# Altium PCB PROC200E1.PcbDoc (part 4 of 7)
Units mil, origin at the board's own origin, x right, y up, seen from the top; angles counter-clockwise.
Board outline 4163.97 x 3505.34 mil, 6 copper layers (Top Layer, GND1, SIG1, PWR, GND2, Bottom), stack 58.132 mil thick; 367 components, 387 nets, 1784 pads, 858 vias.
Unrouted connection lines stored in the file: 17.
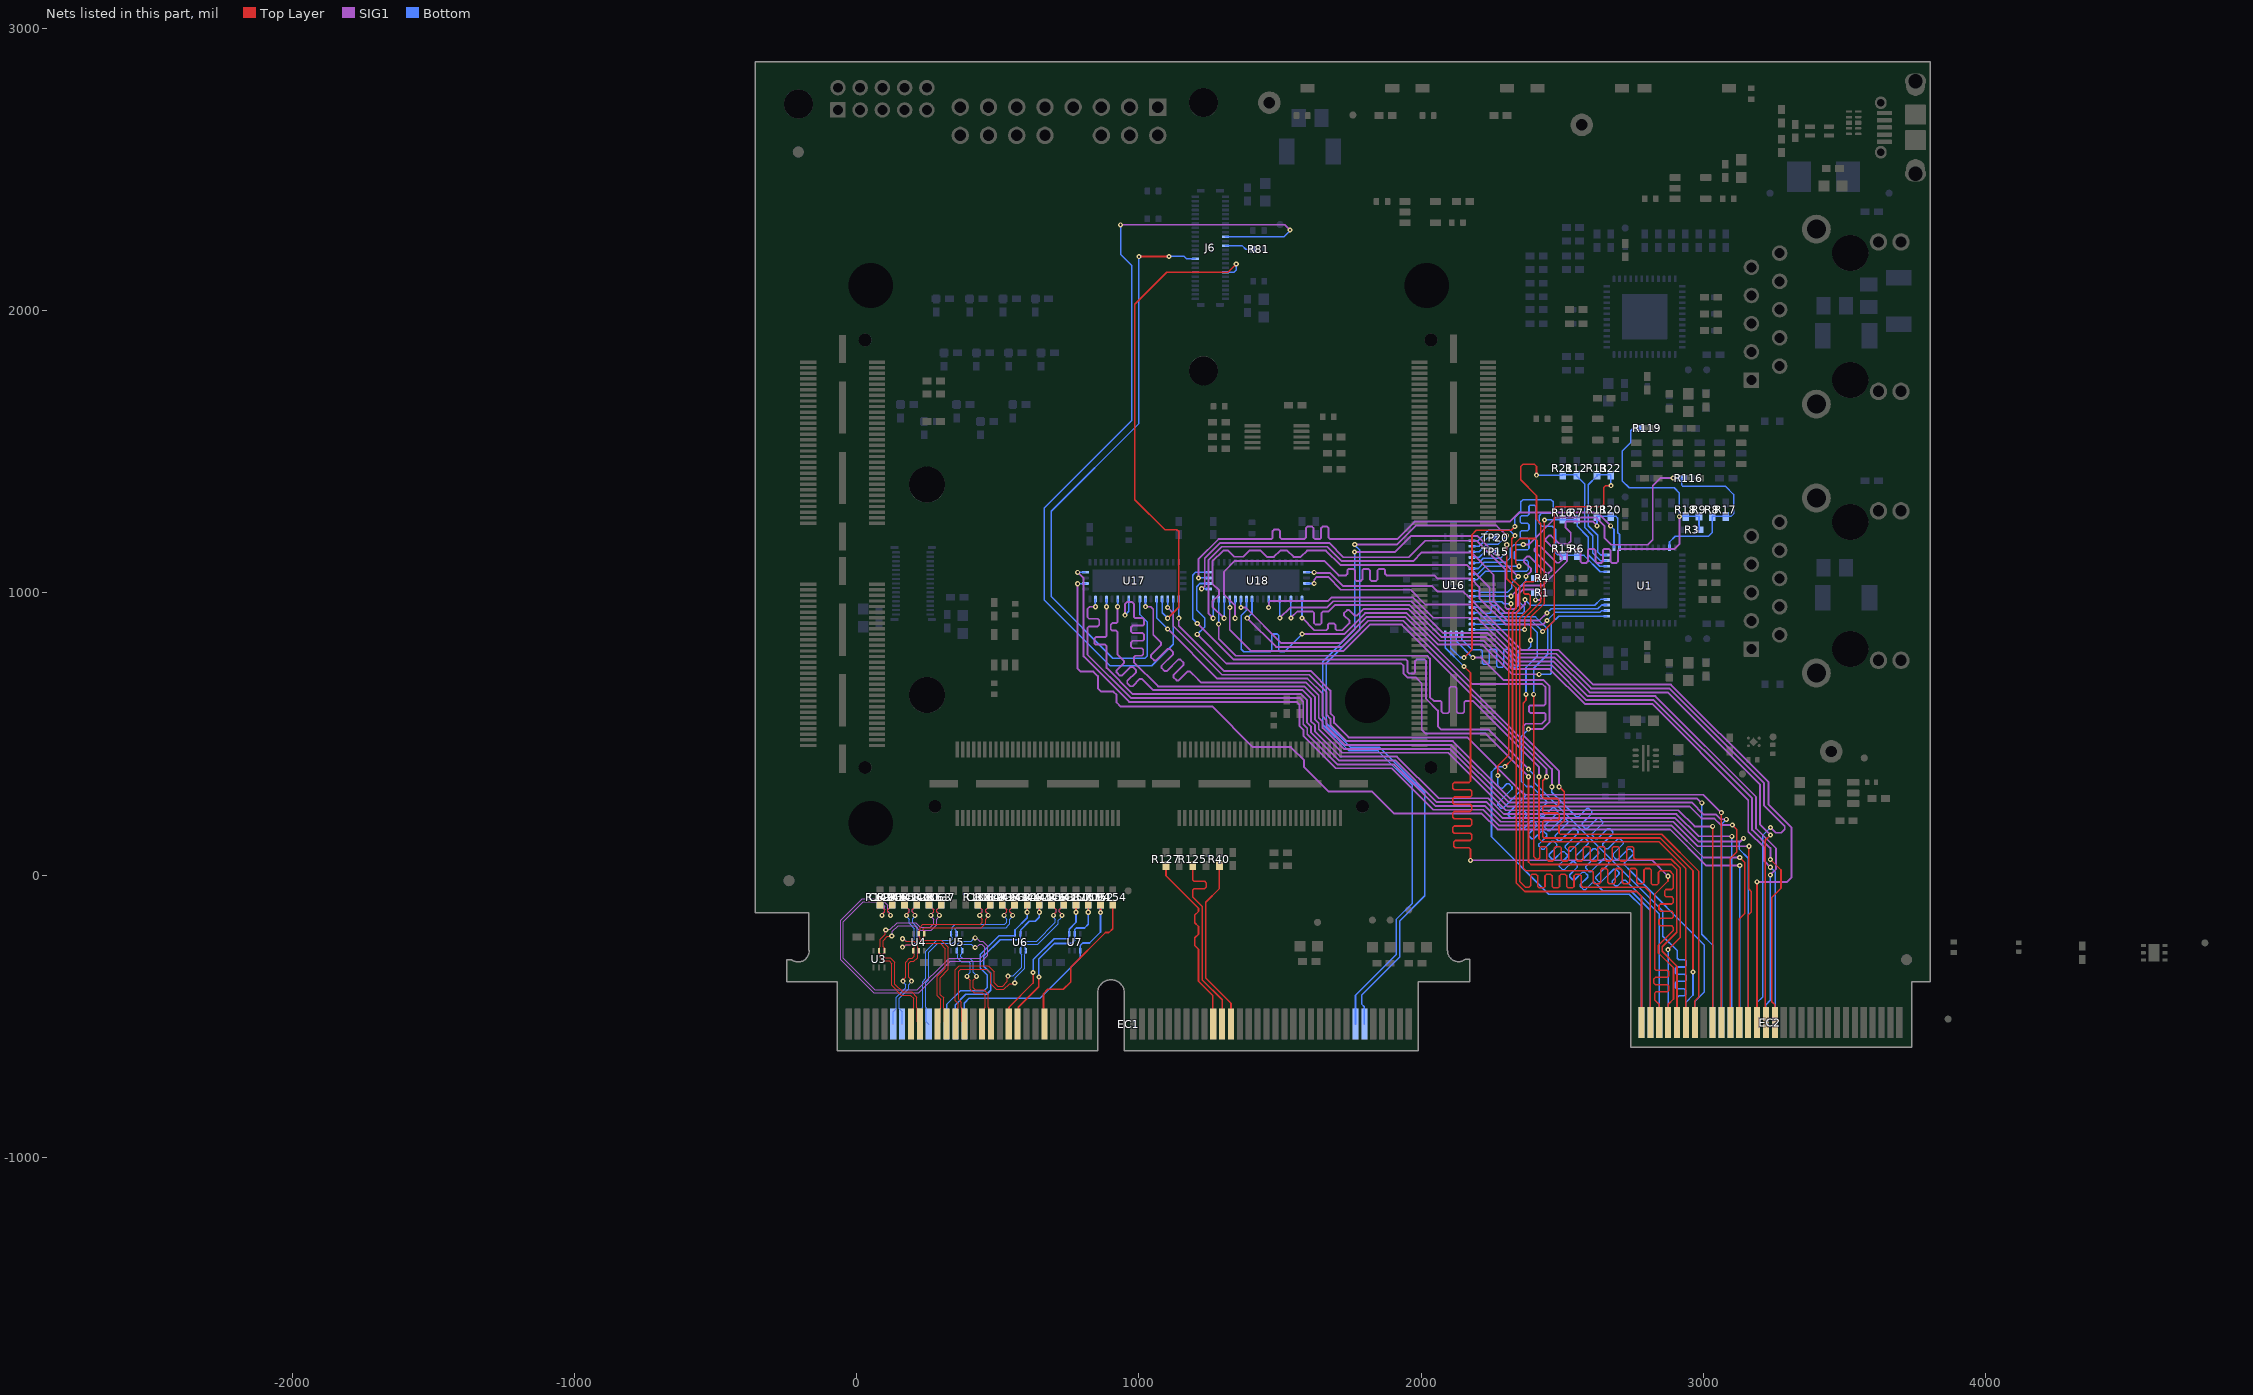
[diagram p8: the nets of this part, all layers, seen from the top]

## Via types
v1: diameter 18, hole 8, Top Layer to Bottom, tented both sides, 729 vias
v2: diameter 19.68, hole 7.87, Top Layer to Bottom, 77 vias
v3: diameter 24, hole 12, Top Layer to Bottom, tented both sides, 52 vias

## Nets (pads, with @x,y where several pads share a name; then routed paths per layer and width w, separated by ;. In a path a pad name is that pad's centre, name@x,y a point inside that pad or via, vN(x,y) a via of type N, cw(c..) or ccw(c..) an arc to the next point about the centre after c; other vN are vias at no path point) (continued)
HSEC_ADC0_AIN2_P: C80.2 EC1.15 R136.2 U3.5 | length 754.3
  Top Layer w4: U3.5@79,-268.47 79,-274.38 83.34,-278.72 83.34,-293.56 93.35,-303.56 114.7,-303.56 124.56,-313.42 124.56,-391.12 158.48,-425.03 190.53,-425.03 202.63,-437.13 202.63,-469.93 201.21,-471.35 201.21,-519.5 EC1.15@192.38,-528.32 ; U3.5@80.94,-266.54 80.94,-256.76 83.34,-254.35 83.34,-227.49 100.94,-209.9 100.94,-196.47 v1(102.9,-194.51) ; R136.2@256.07,-103 256.07,-106.94 272.23,-123.09 272.23,-130.45 262.73,-139.95 v1(262.73,-142.73)
  SIG1 w4.2: v1(102.9,-194.51) 104.7,-192.7 118.7,-192.7 142.86,-168.54 209.31,-168.54 225.56,-184.79 259.84,-184.79 272.63,-172 272.63,-156.36 262.73,-146.46 v1(262.73,-142.73)
  Bottom w4: C80.2@256.07,-103 256.07,-106.94 272.23,-123.09 272.23,-130.45 262.73,-139.95 v1(262.73,-142.73)
HSEC_ADC0_AIN3_N: C63.2 EC1.17 R137.2 U3.4 | length 754
  Top Layer w4: U3.4@96.75,-266.54 U3.4@96.75,-261.45 ; U3.4@97.56,-261.45 96.75,-260.63 96.75,-256.76 94.34,-254.35 94.34,-232.05 108.71,-217.68 122.15,-217.68 v1(124.11,-215.72) ; U3.4@98.69,-268.47 98.69,-274.38 94.34,-278.72 94.34,-289 97.9,-292.56 119.26,-292.56 135.56,-308.86 135.56,-386.56 163.03,-414.03 195.09,-414.03 213.63,-432.58 213.63,-469.93 215.05,-471.35 215.05,-519.5 EC1.17@223.88,-528.32 ; v1(292.73,-142.73) 292.73,-139.95 283.23,-130.45 283.23,-123.09 299.38,-106.94 R137.2@299.38,-103
  SIG1 w4.2: v1(124.11,-215.72) 125.91,-213.91 125.91,-199.91 147.09,-178.74 205.08,-178.74 221.33,-194.99 264.07,-194.99 282.83,-176.22 282.83,-156.36 292.73,-146.46 v1(292.73,-142.73)
  Bottom w4: v1(292.73,-142.73) 292.73,-139.95 283.23,-130.45 283.23,-123.09 299.38,-106.94 C63.2@299.38,-103
HSEC_ADC0_AIN4_P: C81.2 EC1.21 R138.2 U4.2 | length 798.9
  Top Layer w4: EC1.21@286.87,-528.32 295.7,-519.5 295.7,-473.11 297.12,-471.69 297.12,-440.12 288.29,-431.29 285.06,-428.06 285.06,-358.58 314,-329.65 314,-260.85 295.27,-242.12 233.93,-242.12 224.32,-232.52 224.32,-222.66 221.92,-220.25 221.92,-210.47 U4.2@219.98,-208.54 221.92,-206.6 221.92,-196.82 224.32,-194.41 224.32,-184.56 233.93,-174.95 437.4,-174.95 445.46,-166.9 445.46,-156.01 435.96,-146.51 v1(435.96,-142.73) 435.96,-139.95 445.46,-130.45 445.46,-123.09 429.3,-106.94 R138.2@429.3,-103
  Bottom w4: C81.2@429.3,-103 429.3,-106.94 445.46,-123.09 445.46,-130.45 435.96,-139.95 v1(435.96,-142.73)
HSEC_ADC0_AIN5_N: C64.2 EC1.23 R139.2 U4.1 | length 798.9
  Top Layer w4: EC1.23@318.37,-528.32 309.54,-519.5 309.54,-473.11 308.12,-471.69 308.12,-435.56 296.06,-423.51 296.06,-363.14 325,-334.2 325,-263.24 325,-256.29 299.83,-231.12 238.48,-231.12 235.32,-227.96 235.32,-222.66 237.73,-220.25 237.73,-210.47 U4.1@239.67,-208.54 237.73,-206.6 237.73,-196.82 235.32,-194.41 235.32,-189.11 238.48,-185.95 441.96,-185.95 456.46,-171.46 456.46,-156.01 465.96,-146.51 v1(465.96,-142.73) 465.96,-139.95 456.46,-130.45 456.46,-123.09 472.61,-106.94 R139.2@472.61,-103
  Bottom w4: v1(465.96,-142.73) 465.96,-139.95 456.46,-130.45 456.46,-123.09 472.61,-106.94 C64.2@472.61,-103
HSEC_ADC1_AIN0_P: C82.2 EC1.12 R140.2 U4.4 | length 636.2
  Top Layer w4: v1(162.08,-255.56) 164.85,-255.56 174.35,-246.06 199.34,-246.06 204.64,-251.35 204.64,-257.41 202.23,-259.81 U4.4@202.23,-267.59 ; v1(163.76,-376) 163.76,-372.21 173.26,-362.71 173.26,-308.77 187.03,-295 197.36,-295 204.64,-287.72 204.64,-281.71 202.23,-279.31 202.23,-269.53 U4.4@200.3,-267.59 ; v1(206.11,-142.73) 206.11,-139.95 196.61,-130.45 196.61,-123.09 212.77,-106.94 R140.2@212.77,-103
  Bottom w4: EC1.12@129.39,-528.32 129.39,-484.03 139.64,-473.78 139.64,-432.36 173.26,-398.74 173.26,-388.27 163.76,-378.77 v1(163.76,-376) ; v1(162.08,-255.56) 165.87,-255.56 175.37,-246.06 201.14,-246.06 214.9,-232.29 214.9,-185.29 198.52,-168.9 198.52,-154.11 206.11,-146.51 v1(206.11,-142.73) 206.11,-139.95 196.61,-130.45 196.61,-123.09 212.77,-106.94 C82.2@212.77,-103
HSEC_ADC1_AIN1_N: C65.2 EC1.14 R141.2 U4.5 | length 637.8
  Top Layer w4: v1(162.08,-225.56) 164.85,-225.56 174.35,-235.06 203.9,-235.06 215.64,-246.8 215.64,-257.41 218.04,-259.81 U4.5@218.04,-267.59 ; R141.2@169.46,-103 169.46,-106.94 185.61,-123.09 185.61,-130.45 176.11,-139.95 v1(176.11,-142.73) ; v1(193.76,-376) 193.76,-372.21 184.26,-362.71 184.26,-313.32 191.58,-306 201.92,-306 215.64,-292.28 215.64,-281.71 218.04,-279.31 218.04,-269.53 U4.5@219.98,-267.59
  Bottom w4: EC1.14@160.89,-528.32 160.89,-484.03 150.64,-473.78 150.64,-436.92 184.26,-403.3 184.26,-388.27 193.76,-378.77 v1(193.76,-376) ; v1(162.08,-225.56) 165.87,-225.56 175.37,-235.06 196.58,-235.06 203.9,-227.73 203.9,-189.85 185.61,-171.56 185.61,-156.01 176.11,-146.51 v1(176.11,-142.73) 176.11,-139.95 185.61,-130.45 185.61,-123.09 169.46,-106.94 C65.2@169.46,-103
HSEC_ADC1_AIN2_P: C83.2 EC1.18 R142.2 U5.1 | length 755.4
  Top Layer w4: R142.2@515.92,-103 515.92,-106.94 532.07,-123.09 532.07,-130.45 522.57,-139.95 v1(522.57,-142.73)
  Bottom w4: EC1.18@223.88,-528.32 232.71,-519.5 232.71,-469.3 234.13,-467.88 234.13,-377.24 244.87,-366.5 244.87,-269.36 283.11,-231.12 335.65,-231.12 338.81,-227.96 338.81,-222.66 336.41,-220.25 336.41,-210.47 U5.1@334.47,-208.54 336.41,-206.6 336.41,-196.82 338.81,-194.41 338.81,-184.56 348.41,-174.95 524.49,-174.95 526.22,-173.22 532.07,-167.37 532.07,-156.01 522.57,-146.51 v1(522.57,-142.73) 522.57,-139.95 532.07,-130.45 532.07,-123.09 515.92,-106.94 C83.2@515.92,-103
HSEC_ADC1_AIN3_N: C66.2 EC1.20 R143.2 U5.2 | length 755.4
  Top Layer w4: v1(552.57,-142.73) 552.57,-139.95 543.07,-130.45 543.07,-123.09 559.22,-106.94 R143.2@559.22,-103
  Bottom w4: EC1.20@255.38,-528.32 246.55,-519.5 246.55,-469.3 245.13,-467.88 245.13,-381.8 255.87,-371.05 255.87,-273.91 287.67,-242.12 340.21,-242.12 349.81,-232.52 349.81,-222.66 352.22,-220.25 352.22,-210.47 U5.2@354.15,-208.54 352.22,-206.6 352.22,-196.82 349.81,-194.41 349.81,-189.11 352.97,-185.95 529.05,-185.95 537.22,-177.78 543.07,-171.93 543.07,-156.01 552.57,-146.51 v1(552.57,-142.73) 552.57,-139.95 543.07,-130.45 543.07,-123.09 559.22,-106.94 C66.2@559.22,-103
HSEC_ADC1_AIN4: C84.2 EC1.24 R144.2 U6.1 | length 674.2
  Top Layer w5.66: v1(603.87,-131.75) R144.2@603.87,-103
  Bottom w5.66: EC1.24@318.37,-528.32 318.37,-458.74 367.43,-409.68 450.94,-409.68 462.53,-398.08 462.53,-353.86 437.97,-329.3 437.97,-281.2 503.62,-215.55 559.33,-215.55 560.44,-214.44 U6.1@560.44,-208.54 560.86,-208.11 560.86,-194.49 603.87,-151.47 v1(603.87,-131.75) C84.2@603.87,-103
HSEC_ADC1_AIN5: C67.2 EC1.26 R145.2 U6.2 | length 692.4
  Top Layer w5.66: v1(647.18,-131.75) R145.2@647.18,-103
  Bottom w5.66: EC1.26@349.86,-528.32 349.86,-459.35 386.87,-422.34 460.8,-422.34 475.24,-407.9 475.24,-347.85 450.63,-323.25 450.63,-286.57 508.32,-228.88 575.27,-228.88 580.12,-224.02 U6.2@580.12,-208.54 580.81,-207.85 580.81,-194.76 611.8,-163.77 632.74,-163.77 647.18,-149.33 v1(647.18,-131.75) C67.2@647.18,-103
HSEC_ADC2_AIN0_P: C85.2 EC1.25 R146.2 U6.5 | length 896.5
  Top Layer w4: EC1.25@349.86,-528.32 358.69,-519.5 358.69,-469.3 360.11,-467.88 360.11,-455.56 349.97,-445.42 349.97,-335.63 363.73,-321.87 465.42,-321.87 486.53,-342.97 486.53,-381.11 499.41,-394 516.61,-394 533.97,-376.64 533.97,-360.38 v1(535.96,-358.38) ; R146.2@690.49,-103 690.49,-106.94 706.64,-123.09 706.64,-130.45 697.14,-139.95 v1(697.14,-142.73)
  Bottom w4: v1(535.96,-358.38) 537.96,-356.38 554.22,-356.38 584.46,-326.14 584.46,-281.71 582.06,-279.31 582.06,-269.53 U6.5@580.12,-267.59 582.06,-265.65 582.06,-255.87 584.46,-253.47 584.46,-243.61 594.07,-234.01 637.3,-234.01 703.9,-167.4 703.9,-157.05 699.82,-152.97 699.82,-149.19 697.14,-146.51 v1(697.14,-142.73) 697.14,-139.95 706.64,-130.45 706.64,-123.09 690.49,-106.94 C85.2@690.49,-103
HSEC_ADC2_AIN1_N: C68.2 EC1.27 R147.2 U6.4 | length 898.8
  Top Layer w4: EC1.27@381.36,-528.32 372.53,-519.5 372.53,-469.3 371.11,-467.88 371.11,-451 360.97,-440.86 360.97,-340.19 368.29,-332.87 460.87,-332.87 475.53,-347.53 475.53,-385.67 494.86,-405 521.16,-405 541.75,-384.42 558.01,-384.42 v1(560,-382.42) ; v1(727.14,-142.73) 727.14,-139.95 717.64,-130.45 717.64,-123.09 733.8,-106.94 R147.2@733.8,-103
  Bottom w4: v1(560,-382.42) 562,-380.43 562,-364.16 595.46,-330.7 595.46,-281.71 597.87,-279.31 597.87,-269.53 U6.4@599.81,-267.59 597.87,-265.65 597.87,-255.87 595.46,-253.47 595.46,-248.17 598.62,-245.01 641.85,-245.01 714.9,-171.96 714.9,-160.32 722.14,-153.08 722.14,-151.51 724.46,-149.19 724.46,-145.4 v1(727.14,-142.73) 727.14,-139.95 717.64,-130.45 717.64,-123.09 733.8,-106.94 C68.2@733.8,-103
HSEC_ADC2_AIN2_P: C86.2 EC1.31 R148.2 U5.5 | length 1645.1
  Top Layer w4: v1(119.5,-142.73) 119.5,-139.95 110,-130.45 110,-123.09 126.15,-106.94 R148.2@126.15,-103 ; v1(390.64,-358.74) 390.64,-361.56 402.14,-373.06 402.14,-403.99 415.91,-417.76 444.76,-417.76 454.6,-427.6 454.6,-467.88 453.18,-469.3 453.18,-519.5 EC1.31@444.35,-528.32
  SIG1 w4.2: v1(119.5,-142.73) 119.5,-138.99 109.6,-129.09 109.6,-107.01 86.39,-83.8 19.78,-83.8 -57.2,-160.78 -57.2,-299.69 60.41,-417.3 219.59,-417.3 331.64,-305.25 442.2,-305.25 464.2,-283.24 464.2,-251.78 446.83,-234.41 435.47,-234.41 423.57,-222.51 v1(419.83,-222.51)
  Bottom w4: v1(119.5,-142.73) 119.5,-139.95 110,-130.45 110,-123.09 126.15,-106.94 C86.2@126.15,-103 ; v1(390.64,-358.74) 390.64,-355.92 402.14,-344.42 402.14,-312.32 396.19,-306.37 370.82,-306.37 358.5,-294.05 358.5,-281.71 356.09,-279.31 356.09,-269.53 U5.5@354.15,-267.59 356.09,-265.65 356.09,-255.87 358.5,-253.47 358.5,-243.61 368.1,-234.01 405.51,-234.01 417.01,-222.51 v1(419.83,-222.51)
HSEC_ADC2_AIN3_N: C69.2 EC1.33 R149.2 U5.4 | length 1542.3
  Top Layer w4: R149.2@82.85,-103 82.85,-106.94 99,-123.09 99,-130.45 89.5,-139.95 v1(89.5,-142.73) ; v1(424.64,-358.74) 424.64,-361.56 413.14,-373.06 413.14,-399.44 420.46,-406.76 449.32,-406.76 465.6,-423.04 465.6,-467.88 467.02,-469.3 467.02,-519.5 EC1.33@475.85,-528.32
  SIG1 w4.2: v1(89.5,-142.73) 89.5,-138.99 99.4,-129.09 99.4,-111.23 82.17,-94 24,-94 -47,-165 -47,-295.46 64.64,-407.1 215.36,-407.1 321.44,-301.02 327.42,-295.05 437.97,-295.05 454,-279.02 454,-256 442.61,-244.61 435.47,-244.61 423.57,-256.51 v1(419.83,-256.51)
  Bottom w4: C69.2@82.85,-103 82.85,-106.94 99,-123.09 99,-130.45 89.5,-139.95 v1(89.5,-142.73) ; v1(419.83,-256.51) 417.01,-256.51 405.51,-245.01 372.66,-245.01 369.5,-248.17 369.5,-253.47 371.9,-255.87 371.9,-265.65 U5.4@373.84,-267.59 371.9,-269.53 371.9,-279.31 369.5,-281.71 369.5,-289.5 375.37,-295.37 400.75,-295.37 413.14,-307.77 413.14,-344.42 424.64,-355.92 v1(424.64,-358.74)
HSEC_ADC2_AIN4: C87.2 EC1.37 R150.2 U7.1 | length 581.4
  Top Layer w5.66: EC1.37@538.84,-528.32 539.62,-527.54 539.62,-468.03 625,-382.65 v1(625,-345) ; v1(777.1,-131.75) R150.2@777.1,-103
  Bottom w5.66: v1(625,-345) 625,-299.96 699.55,-225.4 748.49,-225.4 751.8,-222.09 751.8,-209.45 U7.1@752.72,-208.54 752.72,-192.07 777.1,-167.68 v1(777.1,-131.75) C87.2@777.1,-103
HSEC_ADC2_AIN5: C70.2 EC1.39 R151.2 U7.2 | length 611
  Top Layer w5.66: EC1.39@570.34,-528.32 572.77,-525.89 572.77,-468.03 645.5,-395.3 v1(645.5,-361.61) ; v1(820.41,-131.75) R151.2@820.41,-103
  Bottom w5.66: v1(645.5,-361.61) 645.5,-297.36 700.24,-242.62 761.94,-242.62 772.4,-232.16 U7.2@772.4,-208.54 772.4,-192.69 777.69,-187.4 807.06,-187.4 820.41,-174.05 v1(820.41,-131.75) C70.2@820.41,-103
HSEC_ADC_CAL0: C94.2 EC1.28 R152.2 U7.4 | length 815.7
  Top Layer w5.66: v1(863.72,-132.78) R152.2@863.72,-103
  Bottom w5.66: EC1.28@381.36,-528.32 381.36,-453.76 399.16,-435.96 650.04,-435.96 792.09,-293.91 U7.4@792.09,-267.59 792.09,-249.91 801.16,-240.84 824.77,-240.84 863.72,-201.89 v1(863.72,-132.78) C94.2@863.72,-103
HSEC_FSIRX0_CLK: EC1.79 R40.1 | length 618.7
  Top Layer w5.66: R40.1@1285.23,33.25 1285.23,-47.9 1236.77,-96.36 1236.77,-364.71 1326.24,-454.19 EC1.79@1326.24,-528.32
HSEC_FSIRX0_DATA0: EC1.75 R127.1 | length 652.4
  Top Layer w5.66: R127.1@1096,33.25 1096,-2.18 1211.03,-117.2 1211.03,-128.87 1198,-141.89 1198,-169.08 1211.03,-182.11 1211.03,-209.3 1198,-222.33 1198,-249.51 1211.03,-262.54 1211.03,-376.07 1261.94,-426.98 1261.94,-527.01 EC1.75@1263.25,-528.32
HSEC_FSIRX0_DATA1: EC1.77 R125.1 | length 687.5
  Top Layer w5.66: R125.1@1190.61,33.25 1190.61,-2.68 1190.61,-17.16 1195.75,-22.29 1232.89,-22.29 1238.02,-27.42 1238.02,-42.82 1232.89,-47.95 1195.75,-47.95 1190.61,-53.08 1190.61,-77.87 1194.32,-81.57 1223.69,-110.94 1223.69,-370.82 1294.75,-441.88 EC1.77@1294.75,-528.32
HSEC_ICSSM_MII0_COL: EC1.110 U16.24 | length 2784.3
  SIG1 w6.66: v1(1764.77,1171.49) 1914.79,1171.49 1981.57,1238.27 2266.89,1238.27 v1(2302.84,1202.32)
  Bottom w5.66: v1(1764.77,1171.49) 1764.77,1168.93 1781.98,1151.72 1781.98,868.42 1664.11,750.55 1664.11,538.04 1749.73,452.41 1852.3,452.41 2012.77,291.95 2012.77,-73.72 1924,-162.49 1924,-290.19 1788.81,-425.38 1788.81,-456.8 1798.68,-466.67 EC1.110@1798.68,-528.32 ; U16.24@2179.94,1145.28 2206.28,1145.28 2233.62,1172.62 2273.14,1172.62 v1(2302.84,1202.32)
HSEC_ICSSM_MII0_CRS: EC2.121 U16.22 | length 2340.8
  Top Layer w5.66: v1(2332.2,1202.58) 2321.23,1191.61 2321.23,1050.03 2349,1022.26 2349,939.25 2336.3,926.55 2336.3,-27.67 2366.81,-58.19 2764.12,-58.19 2780.63,-74.69 EC2.121@2780.63,-522.97
  Bottom w5.66: U16.22@2179.94,1184.65 2201.65,1184.65 2240.63,1223.63 2311.15,1223.63 v1(2332.2,1202.58)
HSEC_ICSSM_MII0_RX_DV: EC2.124 U16.33 | length 2849.1
  Top Layer w5.66: v1(2271.74,352.86) 2271.74,386.67 2310.98,425.91 2310.98,937.04 2317.85,943.91 2317.85,960.96 v1(2318.29,961.4)
  Bottom w5.66: U16.33@2179.94,968.11 2285.6,968.11 2292.31,961.4 v1(2318.29,961.4) ; v1(2271.74,352.86) 2271.74,347.74 2271.74,316.26 2280.65,307.35 2287.91,307.35 2303.73,323.17 2310.99,323.17 2321.87,312.29 2321.87,305.03 2272.11,255.27 2272.11,248.01 2283,237.12 2290.26,237.12 2350.1,296.97 2357.36,296.97 2368.24,286.08 2368.24,278.82 2308.4,218.98 2308.4,211.72 2319.29,200.84 2326.55,200.84 2355.09,229.38 2362.35,229.38 2373.24,218.5 2373.24,211.24 2344.69,182.69 2344.69,175.43 2355.58,164.55 2362.84,164.55 2390.27,191.98 2397.52,191.98 2408.41,181.09 2408.41,173.83 2380.98,146.4 2380.98,139.15 2391.87,128.26 2399.12,128.26 2426.56,155.69 2433.81,155.69 2444.7,144.8 2444.7,137.54 2417.27,110.11 2417.27,102.86 2428.16,91.97 2435.41,91.97 2462.84,119.4 2470.1,119.4 2480.99,108.51 2480.99,101.26 2453.56,73.83 2453.56,66.57 2464.44,55.68 2471.7,55.68 2499.13,83.11 2506.39,83.11 2517.28,72.22 2517.28,64.97 2489.85,37.54 2489.85,30.28 2500.73,19.39 2507.99,19.39 2535.42,46.82 2542.68,46.82 2553.57,35.94 2553.57,28.68 2526.14,1.25 2526.14,-6.01 2537.02,-16.9 2544.28,-16.9 2571.71,10.53 2578.97,10.53 2589.85,-0.35 2589.85,-7.61 2564.1,-33.36 2564.1,-40.62 2574.99,-51.51 2582.25,-51.51 2607.25,-26.5 2614.51,-26.5 2616.51,-28.5 2643.14,-55.13 2742.9,-55.13 2812.13,-124.36 EC2.124@2812.13,-522.97
HSEC_ICSSM_MII0_RXCLK: EC2.123 U16.28 | length 2902
  Top Layer w5.66: v1(2346.26,1094.06) 2334.58,1105.74 2334.58,1176.7 2350.38,1192.5 2403.35,1192.5 2410.45,1185.4 2410.45,1046.21 2403.98,1039.73 2370.54,1039.73 2362.9,1032.09 2362.9,1000.1 2367,996 2381.21,996 2386.59,990.62 2386.59,948.25 2348.96,910.62 2348.96,-22.43 2351.28,-24.75 2369.61,-43.08 2382.47,-43.08 2387.6,-37.95 2387.6,-2.92 2392.73,2.22 2408.13,2.22 2413.26,-2.92 2413.26,-40.4 2418.39,-45.53 2433.79,-45.53 2438.92,-40.4 2438.92,-2.76 2444.05,2.37 2459.45,2.37 2464.58,-2.76 2464.58,-40.4 2469.71,-45.53 2485.11,-45.53 2490.24,-40.4 2490.24,-2.76 2495.37,2.37 2510.77,2.37 2515.9,-2.76 2515.9,-40.4 2521.03,-45.53 2536.43,-45.53 2541.56,-40.4 2541.56,-2.76 2546.69,2.37 2562.09,2.37 2567.22,-2.76 2567.22,-37.95 2572.35,-43.08 2600.84,-43.08 2793.6,-43.08 2812.13,-61.61 EC2.123@2812.13,-522.97
  Bottom w5.66: U16.28@2179.94,1066.54 2200.48,1066.54 2228,1094.06 v1(2346.26,1094.06)
HSEC_ICSSM_MII0_RXD0: EC2.125 U16.42 | length 2882.3
  Top Layer w5.66: v1(2151.97,739.22) 2174.65,716.54 2174.65,361.44 2174.65,332.95 2169.52,327.82 2117.21,327.82 2112.08,322.69 2112.08,307.29 2117.21,302.16 2173.95,302.16 2179.08,297.03 2179.08,281.63 2173.95,276.5 2117.21,276.5 2112.08,271.37 2112.08,255.97 2117.21,250.84 2173.95,250.84 2179.08,245.71 2179.08,230.31 2173.95,225.18 2117.21,225.18 2112.08,220.05 2112.08,204.65 2117.21,199.52 2173.95,199.52 2179.08,194.39 2179.08,178.99 2173.95,173.86 2117.21,173.86 2112.08,168.73 2112.08,153.33 2117.21,148.2 2173.95,148.2 2179.08,143.07 2179.08,127.67 2173.95,122.54 2120.41,122.54 2115.28,117.41 2115.28,102.01 2120.41,96.88 2169.52,96.88 2174.65,91.75 2174.65,55.45 v1(2174.65,52.27) ; EC2.125@2843.62,-522.97 2843.62,-458 2833.23,-447.61 2827,-441.38 2827,-419.12 2832.13,-413.99 2871.87,-413.99 2877,-408.86 2877,-393.46 2871.87,-388.33 2829.92,-388.33 2824.79,-383.2 2824.79,-367.8 2829.92,-362.67 2871.87,-362.67 2877,-357.54 2877,-342.14 2871.87,-337.01 2832.13,-337.01 2827,-331.88 2827,-290 2827,-68.53 2874.58,-20.95 v1(2874.58,-4.16)
  SIG1 w6.66: v1(2174.65,52.27) 2818.15,52.27 v1(2874.58,-4.16)
  Bottom w5.66: U16.42@2085.45,853.94 2085.45,805.74 v1(2151.97,739.22)
HSEC_ICSSM_MII0_RXD1: EC2.126 U16.40 | length 2872.1
  SIG1 w6.66: v1(2183,770.25) 2213.13,770.25 2292.37,691 2434.39,691 2454.43,670.96 2454.43,541.99 2429.33,516.9 v1(2380.46,516.9)
  Bottom w5.66: U16.40@2124.82,853.94 2124.82,828.42 v1(2183,770.25) ; v1(2380.46,516.9) 2355.24,491.68 2355.24,331.5 2372.95,313.79 2391.88,313.79 2425.8,279.86 2444.17,261.5 2444.17,254.24 2415.51,225.58 2415.51,218.32 2426.4,207.44 2433.65,207.44 2465.03,238.81 2472.29,238.81 2483.17,227.92 2483.17,220.67 2438.59,176.08 2438.59,168.82 2449.47,157.93 2456.73,157.93 2501.32,202.52 2508.57,202.52 2519.46,191.63 2519.46,184.38 2474.87,139.79 2474.87,132.53 2485.76,121.65 2493.02,121.65 2537.61,166.23 2544.86,166.23 2555.75,155.35 2555.75,148.09 2511.16,103.5 2511.16,96.24 2522.05,85.36 2529.31,85.36 2573.89,129.94 2581.15,129.94 2592.04,119.06 2592.04,111.8 2547.45,67.21 2547.45,59.95 2558.34,49.07 2565.6,49.07 2610.18,93.66 2617.44,93.66 2628.33,82.77 2628.33,75.51 2583.74,30.92 2583.74,23.67 2594.63,12.78 2601.88,12.78 2646.47,57.37 2653.73,57.37 2664.62,46.48 2664.62,39.22 2619.28,-6.11 2619.28,-13.37 2630.17,-24.26 2637.43,-24.26 2682.76,21.08 2690.02,21.08 2700.91,10.19 2700.91,2.93 2677.27,-20.7 2677.27,-27.96 2688.16,-38.85 2695.41,-38.85 2716.33,-17.93 2723.59,-17.93 2725.59,-19.93 2843.62,-137.96 EC2.126@2843.62,-522.97
HSEC_ICSSM_MII0_RXD2: EC2.127 U16.37 | length 2910.3
  Top Layer w5.66: v1(2371.38,640.29) 2371.38,618.91 2361.62,609.15 2361.62,25.04 2371.45,15.2 2555.8,15.2 2604.97,15.2 2610.1,10.07 2610.1,-25.29 2615.23,-30.42 2630.63,-30.42 2635.76,-25.29 2635.76,18.18 2640.89,23.31 2656.29,23.31 2661.42,18.18 2661.42,-25.29 2666.55,-30.42 2681.95,-30.42 2687.08,-25.29 2687.08,18.18 2692.21,23.31 2707.61,23.31 2712.74,18.18 2712.74,-25.29 2717.87,-30.42 2733.27,-30.42 2738.4,-25.29 2738.4,18.18 2743.53,23.31 2758.93,23.31 2764.06,18.18 2764.06,-25.29 2769.19,-30.42 2784.59,-30.42 2789.72,-25.29 2789.72,18.18 2794.85,23.31 2810.25,23.31 2815.38,18.18 2815.38,-29.67 2820.51,-34.8 2835.91,-34.8 2841.04,-29.67 2841.04,10.07 2846.17,15.2 2849,15.2 2880.44,15.2 2892.63,3.01 2892.63,-33.06 2892.63,-45.92 2887.5,-51.06 2867.51,-51.06 2862.38,-56.19 2862.38,-71.58 2867.51,-76.72 2887.5,-76.72 2892.63,-81.85 2892.63,-97.24 2887.5,-102.38 2847.77,-102.38 2842.63,-107.51 2842.63,-122.9 2847.77,-128.04 2887.5,-128.04 2892.63,-133.17 2892.63,-148.56 2887.5,-153.7 2847.77,-153.7 2842.63,-158.83 2842.63,-174.22 2847.77,-179.36 2887.5,-179.36 2892.63,-184.49 2892.63,-187.32 2892.63,-197.22 2841.07,-248.78 2841.07,-275.99 2893.95,-328.88 2893.95,-439.16 2875.12,-458 EC2.127@2875.12,-522.97
  Bottom w5.66: U16.37@2179.94,889.37 2381.66,889.37 2411.41,859.63 2411.41,775.55 2371.38,735.52 v1(2371.38,640.29)
HSEC_ICSSM_MII0_RXD3: EC2.128 U16.35 | length 2835.5
  Top Layer w5.66: v1(2398.76,640.29) 2398.76,65.48 2407.78,56.46 2410.82,56.46 2414.87,56.46 2420,61.6 2420,95.72 2425.13,100.85 2440.53,100.85 2445.66,95.72 2445.66,55.09 2450.79,49.95 2466.19,49.95 2471.32,55.09 2471.32,95.72 2476.45,100.85 2491.85,100.85 2496.98,95.72 2496.98,55.09 2502.11,49.95 2517.51,49.95 2522.64,55.09 2522.64,95.72 2527.77,100.85 2543.17,100.85 2548.3,95.72 2548.3,55.09 2553.43,49.95 2568.83,49.95 2573.96,55.09 2573.96,95.72 2579.09,100.85 2594.49,100.85 2599.62,95.72 2599.62,55.09 2604.75,49.95 2620.15,49.95 2625.28,55.09 2625.28,95.72 2630.41,100.85 2645.81,100.85 2650.94,95.72 2650.94,55.09 2656.07,49.95 2671.47,49.95 2676.6,55.09 2676.6,95.72 2681.73,100.85 2697.13,100.85 2702.26,95.72 2702.26,55.09 2707.39,49.95 2722.79,49.95 2727.92,55.09 2727.92,95.72 2733.05,100.85 2748.45,100.85 2753.58,95.72 2753.58,61.6 2758.71,56.46 2787.2,56.46 2886.15,56.46 2917.95,24.66 2917.95,-221.21 v1(2874.8,-264.36)
  Bottom w5.66: U16.35@2179.94,928.74 2202.21,928.74 2216.26,914.69 2405.33,914.69 2448.36,871.66 2448.36,782.8 2398.76,733.2 v1(2398.76,640.29) ; EC2.128@2875.12,-522.97 v1@2875.12,-264.68
HSEC_ICSSM_MII0_RXER: EC1.108 U16.31 | length 2857.1
  SIG1 w6.66: v1(1764.15,1144.33) 1906.95,1144.33 1963.62,1201 2200.56,1201 v1(2343.88,1057.68)
  Bottom w5.66: v1(1764.15,1144.33) 1764.15,1060.53 1764.15,868.5 1651.45,755.8 1651.45,532.79 1744.49,439.75 1847.06,439.75 1968.96,317.86 1968.96,-99.63 1911.04,-157.55 1911.04,-281.96 1767.19,-425.81 EC1.108@1767.19,-528.32 ; U16.31@2179.94,1007.48 2201.13,1007.48 2207.21,1001.39 2305.05,1001.39 2321,1017.34 2321,1034.8 v1(2343.88,1057.68)
HSEC_ICSSM_MII0_RXLINK: EC2.122 U16.26 | length 2312
  Top Layer w5.66: v1(2296.39,383.98) 2323.64,411.22 2323.64,931.8 2336.12,944.28 2336.12,1017.24 2303.11,1050.25 v1(2303.11,1170.3)
  Bottom w5.66: U16.26@2179.94,1105.91 2204.04,1105.91 2220.38,1122.24 2281.07,1122.24 2303.11,1144.29 v1(2303.11,1170.3) ; v1(2296.39,383.98) 2267.83,383.98 2249.14,365.28 2249.14,135.56 2452.5,-67.79 2737.65,-67.79 2780.63,-110.77 EC2.122@2780.63,-522.97
HSEC_ICSSM_MII0_TXCLK: EC2.129 U18.40 | length 3157.5
  Top Layer w5.66: v1(2380.46,348.21) 2380.46,46.1 2389.26,37.29 2887.41,37.29 2905.29,19.41 2905.29,-202.46 2853.73,-254.03 2853.73,-269.96 2906.61,-322.84 EC2.129@2906.61,-522.97
  SIG1 w6.66: v1(1206.72,852.92) 1310.04,749.6 1929.4,749.6 1938,741 1938,713.78 1951.51,700.27 1980.73,700.27 2002.26,678.74 2002.26,514.4 2014.94,501.72 2226.95,501.72 v1(2380.46,348.21)
  Bottom w5.66: v1(1206.72,852.92) 1232.83,879.03 1232.83,911.14 1204.57,939.4 1204.57,1021.92 1215.84,1033.2 U18.40@1247.2,1033.2
HSEC_ICSSM_MII0_TXD0: EC2.131 U18.37 | length 3157.7
  Top Layer w5.66: v1(2417.62,348.21) 2417.62,129.03 2427.92,118.72 2841.79,118.72 2938.11,22.4 EC2.131@2938.11,-522.97
  SIG1 w6.66: v1(1282.63,888.96) 1282.63,837.36 1342.92,777.07 2021.19,777.07 2031.26,767.01 2031.26,630.81 2044.81,617.26 2052.52,617.26 2067.36,617.26 2072.7,611.93 2072.7,578.85 2078.03,573.52 2094.02,573.52 2099.36,578.85 2099.36,661.93 2104.69,667.26 2120.68,667.26 2126.02,661.93 2126.02,578.56 2131.35,573.23 2147.34,573.23 2152.68,578.56 2152.68,611.93 2158.01,617.26 2161.34,617.26 2182.42,617.26 2417.62,382.06 v1(2417.62,348.21)
  Bottom w5.66: v1(1282.63,888.96) U18.37@1282.63,978.08
HSEC_ICSSM_MII0_TXD1: EC2.132 U18.35 | length 3096.4
  Top Layer w5.66: v1(2444.63,348.21) 2430.9,334.47 2430.9,302.46 2430.9,276.48 2436.03,271.35 2482.78,271.35 2487.91,266.21 2487.91,250.82 2482.78,245.69 2435.41,245.69 2430.28,240.55 2430.28,225.16 2435.41,220.03 2483.97,220.03 2489.1,214.89 2489.1,199.5 2483.97,194.37 2436.03,194.37 2430.9,189.23 2430.9,160.74 2430.9,135.84 2435.36,131.38 2847.04,131.38 2963.22,15.19 v1(2963.22,-343.5)
  SIG1 w6.66: v1(1322,948.04) 1322,868.58 1396.07,794.5 1725.46,794.5 1818.27,887.31 1931.69,887.31 2444.63,374.37 v1(2444.63,348.21)
  Bottom w5.66: v1(1322,948.04) U18.35@1322,978.08 ; EC2.132@2938.11,-522.97 2938.11,-450.3 2963.22,-425.18 v1(2963.22,-343.5)
HSEC_ICSSM_MII0_TXD2: EC2.133 U18.33 | length 3151.9
  Top Layer w5.66: v1(2489.02,312.86) 2506.8,295.08 2506.8,193.54 2488.52,175.27 2488.52,149.27 2493.4,144.39 2852.24,144.39 2984.15,12.48 2984.15,-431.54 2969.61,-446.09 EC2.133@2969.61,-522.97
  SIG1 w6.66: v1(1361.37,948.04) 1378.33,948.04 1504.54,821.82 1714.14,821.82 1806.95,914.63 1943,914.63 2180.64,677 2428.77,677 2440.77,665 2440.77,636.73 2440.77,606.74 2435.43,601.4 2386.91,601.4 2381.58,596.07 2381.58,580.08 2386.91,574.74 2435.43,574.74 2440.77,569.41 2440.77,549.77 2431.84,540.84 2427,536 2370.9,536 2362.13,527.23 2362.13,495.51 2489.02,368.62 v1(2489.02,312.86)
  Bottom w5.66: v1(1361.37,948.04) U18.33@1361.37,978.08
HSEC_ICSSM_MII0_TXD3: EC2.134 U18.31 | length 3119.4
  SIG1 w6.66: v1(1383.81,910.25) 1485.89,808.16 1719.8,808.16 1812.61,900.97 1937.35,900.97 2462.96,375.35 v1@2462.96,312.86
  Bottom w5.66: v1(1383.81,910.25) 1400.74,927.18 U18.31@1400.74,978.08 ; v1(2462.9,312.86) 2462.9,293.1 2530.22,225.78 2549.9,206.1 2557.16,206.1 2586.97,235.91 2594.23,235.91 2605.12,225.03 2605.12,217.77 2570.75,183.41 2570.75,176.15 2581.64,165.26 2588.9,165.26 2624.67,201.03 2631.93,201.03 2642.82,190.15 2642.82,182.89 2607.04,147.12 2607.04,139.86 2617.93,128.97 2625.19,128.97 2660.96,164.75 2668.22,164.75 2679.1,153.86 2679.1,146.6 2643.33,110.83 2643.33,103.57 2654.22,92.69 2661.48,92.69 2697.25,128.46 2704.51,128.46 2715.39,117.57 2715.39,110.31 2679.62,74.54 2679.62,67.28 2690.51,56.4 2697.77,56.4 2733.54,92.17 2740.79,92.17 2751.68,81.28 2751.68,74.02 2720.46,42.8 2720.46,35.54 2740.6,15.4 3002.48,-246.48 3002.48,-414.94 2969.61,-447.82 EC2.134@2969.61,-522.97
HSEC_ICSSM_MII0_TXEN: EC2.130 U18.42 | length 3119.7
  SIG1 w6.66: v1(1206.72,891.67) 1335.12,763.26 1916.51,763.26 1946.5,763.26 1951.83,757.93 1951.83,719.26 1957.17,713.93 1973.16,713.93 1978.49,719.26 1978.49,757.93 1983.83,763.26 2010,763.26 2012.32,763.26 2017.14,758.44 2017.14,624.86 2059,583 2059,527.38 2071,515.38 2240.24,515.38 v1(2380.46,375.15)
  Bottom w5.66: v1(1206.72,891.67) 1190.51,907.87 1190.51,1062.51 1200.57,1072.57 U18.42@1247.2,1072.57 ; v1(2380.46,375.15) 2399.79,355.83 2399.79,329.21 2856.28,-127.28 2856.28,-216.58 2907.2,-267.49 2907.2,-292 2907.2,-294.83 2912.33,-299.96 2933.85,-299.96 2938.98,-305.09 2938.98,-320.49 2933.85,-325.62 2904.82,-325.62 2899.69,-330.75 2899.69,-346.15 2904.82,-351.28 2933.85,-351.28 2938.98,-356.41 2938.98,-371.81 2933.85,-376.94 2904.82,-376.94 2899.69,-382.07 2899.69,-397.47 2904.82,-402.6 2931.53,-402.6 2936.66,-407.73 2936.66,-423.13 2931.53,-428.26 2912.33,-428.26 2907.2,-433.39 2907.2,-448.9 2907.2,-522.39 EC2.130@2906.61,-522.97
HSEC_ICSSM_MII1_COL: EC2.138 U17.24 | length 3090.3
  SIG1 w6.66: v1(1101.87,948.04) 1121.6,928.31 1121.6,882.47 1294.34,709.74 1602.95,709.74 1664.87,647.82 1664.87,567.68 1678.13,554.41 1678.13,532.98 1736.72,474.4 2112.6,474.4 2316.17,270.83 2978,270.83 2993.02,255.81 v1(2994.54,255.81)
  Bottom w5.66: v1(1101.87,948.04) U17.24@1101.87,978.08 ; v1(2994.54,255.81) 2994.54,-209.54 3032.6,-247.6 EC2.138@3032.6,-522.97
HSEC_ICSSM_MII1_CRS: EC2.139 U17.22 | length 3095.2
  Top Layer w5.66: v1(3063.59,221.08) 3063.59,205.11 3063.41,204.93 3063.41,-132.79 3063.59,-132.97 3063.59,-522.47 EC2.139@3064.09,-522.97
  SIG1 w6.66: v1(1141.24,910.32) 1141.24,882.9 1300.75,723.4 1608.6,723.4 1678.53,653.47 1678.53,573.34 1691.79,560.07 1691.79,539.33 1743.07,488.06 2162.47,488.06 2366.04,284.49 3000.18,284.49 v1(3063.59,221.08)
  Bottom w5.66: v1(1141.24,910.32) U17.22@1141.24,978.08
HSEC_ICSSM_MII1_RX_DV: EC2.142 U17.33 | length 3576.8
  SIG1 w6.66: v1(924.71,950.55) 924.71,910 924.71,898.32 919.37,892.98 905.66,892.98 900.33,887.65 900.33,871.66 905.66,866.32 919.37,866.32 924.71,860.99 924.71,857.66 924.71,795.65 924.71,780.81 946.68,758.83 946.68,751.29 920.77,725.38 920.77,717.84 932.08,706.53 939.62,706.53 970.84,737.74 978.38,737.74 989.69,726.43 989.69,718.89 958.47,687.68 958.47,680.14 969.79,668.83 977.33,668.83 1003.24,694.74 1010.78,694.74 1013.13,692.38 1050.42,655.1 1580.31,655.1 1609.61,625.8 1609.61,545.66 1623.49,531.78 1623.49,510.35 1714.2,419.64 1914.15,419.64 2061.5,272.29 2237.44,272.29 2293.54,216.19 2904.31,216.19 2983.16,137.34 v1(3100.71,137.34)
  Bottom w5.66: v1@924.49,950.76 U17.33@924.49,977.86 ; EC2.142@3095.59,-522.97 3100.71,-517.85 v1(3100.71,137.34)
HSEC_ICSSM_MII1_RXCLK: EC2.141 U17.28 | length 3605.1
  Top Layer w5.66: EC2.141@3095.59,-522.97 3095.59,58.55 3118.54,81.5 3118.54,161.61 v1(3102.52,177.63)
  SIG1 w6.66: v1(1023.13,950.89) 1041.93,950.89 1050.75,942.07 1050.75,851.54 1057.57,844.72 1059.92,842.36 1078.77,823.51 1078.77,815.97 1042.28,779.48 1042.28,771.94 1053.59,760.62 1061.13,760.62 1101.99,801.49 1109.53,801.49 1120.84,790.18 1120.84,782.64 1079.98,741.77 1079.98,734.23 1091.29,722.92 1098.83,722.92 1139.7,763.79 1147.24,763.79 1158.55,752.48 1158.55,744.94 1121.91,708.3 1121.91,700.75 1133.22,689.44 1140.76,689.44 1173.03,721.72 1180.57,721.72 1209.29,693 1211.64,690.64 1219.87,682.42 1591.63,682.42 1636.93,637.11 1636.93,556.98 1650.81,543.09 1650.81,521.66 1725.52,446.96 2101.4,446.96 2304.85,243.51 2950.77,243.51 2993.91,200.37 3039.06,200.37 3061.8,177.63 v1(3102.52,177.63)
  Bottom w5.66: v1(1023.13,950.89) U17.28@1023.13,978.08
HSEC_ICSSM_MII1_RXD0: EC2.143 U17.42 | length 3610.9
  Top Layer w5.66: EC2.143@3127.09,-522.97 3127.09,-155.35 3146.6,-135.83 3146.6,44.37 v1(3128.77,62.2)
  SIG1 w6.66: v1(783,1072.57) 804.13,1051.44 804.13,774.56 965.03,613.66 1558.97,613.66 1568.63,604 1568.63,528.69 1582.51,514.8 1582.51,493.37 1697.23,378.66 1896.28,378.66 2043.63,231.31 2220.46,231.31 2276.56,175.21 2887.34,175.21 3000.34,62.2 v1(3128.77,62.2)
  Bottom w5.66: v1@783.22,1072.78 U17.42@810.32,1072.78
HSEC_ICSSM_MII1_RXD1: EC2.144 U17.40 | length 3576.1
  SIG1 w6.66: v1(782.89,1032.18) 782.89,731.79 793.7,720.98 838.39,720.98 854.69,704.68 854.69,662.39 867.3,649.77 909.6,649.77 920.69,638.68 920.69,611.4 935.25,596.83 1260.81,596.83 1403.95,453.69 1538.6,453.69 1585.44,406.85 1585.44,382.64 1672.28,295.8 1826.02,295.8 1904.17,217.65 2214.81,217.65 2270.91,161.55 2881.68,161.55 3009.09,34.14 v1(3128.77,34.14)
  Bottom w5.66: v1(782.89,1032.18) 783.4,1032.69 810.03,1032.69 U17.40@810.53,1033.2 ; EC2.144@3127.09,-522.97 3128.77,-521.29 v1(3128.77,34.14)
HSEC_ICSSM_MII1_RXD2: EC2.145 U17.37 | length 3609.5
  Top Layer w5.66: EC2.145@3158.58,-522.97 3158.58,-141.76 3169,-131.34 3169,-57.09 3160.76,-48.85 3160.76,100.76 v1(3162,102)
  SIG1 w6.66: v1(845.97,950.55) 825.13,950.55 817.79,943.21 817.79,926.18 817.79,913.31 823.12,907.98 854.15,907.98 859.48,902.65 859.48,886.65 854.15,881.32 823.12,881.32 817.79,875.99 817.79,846 817.79,781.17 971.18,627.78 1569,627.78 1582.29,614.48 1582.29,534.34 1596.17,520.46 1596.17,499.03 1702.89,392.32 1902.84,392.32 2050.19,244.97 2226.12,244.97 2282.22,188.87 2892.99,188.87 2979.86,102 v1(3162,102)
  Bottom w5.66: v1@845.75,950.76 U17.37@845.75,977.86
HSEC_ICSSM_MII1_RXD3: EC2.146 U17.35 | length 3565.6
  SIG1 w6.66: v1(885.34,950.55) 885.34,874.27 885.34,848.65 880,843.32 847.52,843.32 842.19,837.99 842.19,821.99 847.52,816.66 880,816.66 885.34,811.33 885.34,808 885.34,733.96 977.86,641.44 1574.66,641.44 1595.95,620.14 1595.95,540 1609.83,526.12 1609.83,504.69 1708.54,405.98 1908.49,405.98 2055.84,258.63 2231.78,258.63 2287.88,202.53 2898.65,202.53 2982.17,119.01 3130.81,119.01 v1(3141.9,130.1)
  Bottom w5.66: v1@885.12,950.76 U17.35@885.12,977.86 ; v1(3141.9,130.1) 3126.44,114.65 3126.44,92.03 3158.58,59.89 EC2.146@3158.58,-522.97
HSEC_ICSSM_MII1_RXER: EC2.137 U17.31 | length 3608.1
  Top Layer w5.66: EC2.137@3032.6,-522.97 3029.19,-519.56 3032.97,-515.78 v1(3032.97,172.65)
  SIG1 w6.66: v1(950.4,920.9) 950.4,960.08 958.31,968 975,968 982.32,960.68 982.32,919 982.32,915.67 987.65,910.34 1012.94,910.34 1018.27,905.01 1018.27,889.01 1012.94,883.68 977.79,883.68 972.46,878.35 972.46,862.35 977.79,857.02 1012.94,857.02 1018.27,851.69 1018.27,835.69 1012.94,830.36 977.79,830.36 972.46,825.03 972.46,809.03 977.79,803.7 1010,803.7 1015.33,798.37 1015.33,782.37 1010,777.04 987.65,777.04 982.32,771.71 982.32,754.37 1067.93,668.76 1585.97,668.76 1623.27,631.46 1623.27,551.32 1637.15,537.44 1637.15,516 1719.86,433.3 2095.75,433.3 2299.2,229.85 2911.41,229.85 2968.61,172.65 v1(3032.97,172.65)
  Bottom w5.66: v1(950.4,920.9) 964.08,934.58 U17.31@964.08,978.08
HSEC_ICSSM_MII1_RXLINK: EC2.140 U17.26 | length 3168.2
  SIG1 w6.66: v1(1101.87,872.04) 1277.83,696.08 1597.29,696.08 1650.59,642.77 1650.59,562.64 1664.47,548.75 1664.47,527.32 1731.18,460.62 2107.06,460.62 2310.51,257.17 2958.01,257.17 3001.15,214.03 3044.72,214.03 3061.21,197.54 v1(3081.24,197.54)
  Bottom w5.66: U17.26@1062.5,978.08 1062.5,911.41 v1(1101.87,872.04) ; EC2.140@3064.09,-522.97 3064.09,180.39 v1(3081.24,197.54)
HSEC_ICSSM_MII1_TXCLK: EC2.147 U18.18 | length 2944.1
  Top Layer w5.66: EC2.147@3190.08,-522.97 v1(3190.08,-24)
  SIG1 w6.66: v1(1621,1072.57) 1622.95,1070.62 1676.92,1070.62 1722.67,1024.87 2037.13,1024.87 2057,1005 2148.32,1005 2153.05,1000.28 2153.43,1000.28 2164.66,989.04 2164.66,988.66 2355.39,797.93 2486.08,797.93 2609.23,674.79 2884.85,674.79 3231.06,328.58 3231.06,249.88 3312.58,168.35 3312.58,-7.82 3296.4,-24 v1(3190.08,-24)
  Bottom w5.66: U18.18@1593.65,1072.57 v1(1621,1072.57)
HSEC_ICSSM_MII1_TXD0: EC2.149 U18.28 | length 2938.8
  Top Layer w5.66: EC2.149@3221.58,-522.97 3219.32,-520.71 3219.32,123.32 v1(3238,142)
  SIG1 w6.66: v1(1459.8,948.04) 1459.8,965.73 1465.61,971.55 1670.6,971.55 1682.81,983.77 1970.46,983.77 2042.38,911.85 2199.12,911.85 2340.35,770.61 2473.38,770.61 2596.53,647.47 2873.53,647.47 3200.71,320.29 3200.71,178.42 3237.14,142 v1(3238,142)
  Bottom w5.66: v1(1459.8,948.04) U18.28@1459.8,978.08
HSEC_ICSSM_MII1_TXD1: EC2.150 U18.26 | length 2910.3
  SIG1 w6.66: v1(1499.17,910.92) 1536.13,947.88 1666.24,947.88 1688.47,970.11 1964.8,970.11 2077.17,857.73 2233.91,857.73 2334.69,756.95 2467.72,756.95 2590.87,633.81 2823.88,633.81 2829.83,633.81 3186.41,277.22 3186.41,271.27 3186.41,165.47 3257.23,94.66 3257.23,20.57 v1(3237.15,0.5)
  Bottom w5.66: v1(1499.17,910.92) U18.26@1499.17,978.08 ; EC2.150@3221.58,-522.97 3221.58,-459.42 3237.29,-443.71 v1@3237.29,0.5
HSEC_ICSSM_MII1_TXD2: EC2.151 U18.24 | length 2938.6
  Top Layer w5.66: v1@3237.97,55.14 3274.96,18.15 3274.96,-46.95 3242.56,-79.35 3242.56,-448.4 3253.07,-458.92 EC2.151@3253.07,-522.97
  SIG1 w6.66: v1(1538.54,910.92) 1561.84,934.22 1585.01,934.22 1615,934.22 1620.34,928.89 1620.34,893.14 1625.67,887.8 1641.66,887.8 1647,893.14 1647,928.89 1652.33,934.22 1671.9,934.22 1688,950.32 1694.13,956.45 1959.14,956.45 2071.52,844.07 2228.25,844.07 2329.04,743.29 2462.06,743.29 2585.21,620.15 2818.22,620.15 2824.17,620.15 3172.75,271.56 3172.75,265.61 3172.75,159.81 3237.15,95.41 v1(3237.15,55.14)
  Bottom w5.66: v1(1538.54,910.92) U18.24@1538.54,978.08
HSEC_ICSSM_MII1_TXD3: EC2.152 U18.22 | length 2909.1
  SIG1 w6.66: v1(1577.91,910.92) 1621.28,867.54 1660.64,867.54 1663.97,867.54 1669.3,872.87 1669.3,886.65 1674.63,891.99 1690.63,891.99 1695.96,886.65 1695.96,872.87 1701.29,867.54 1720.96,867.54 1743.69,890.28 1743.8,890.39 1746.16,892.74 1746.16,900.28 1726.27,920.17 1726.27,927.71 1737.59,939.02 1745.13,939.02 1765.01,919.14 1772.55,919.14 1786.11,932.7 1796.2,942.79 1953.48,942.79 2065.86,830.41 2222.6,830.41 2323.38,729.63 2456.41,729.63 2579.55,606.49 2818.51,606.49 3159.09,265.91 3159.09,154.15 3215,98.25 3215,49.97 v1(3237.15,27.82)
  Bottom w5.66: v1(1577.91,910.92) U18.22@1577.91,978.08 ; v1@3237.21,28.28 3254.98,10.52 3254.98,-521.06 EC2.152@3253.07,-522.97
HSEC_ICSSM_MII1_TXEN: EC2.148 U18.20 | length 2910.3
  SIG1 w6.66: v1(1621,1032.95) 1621,1046.64 1630.63,1056.27 1670.05,1056.27 1715.24,1011.09 1962.46,1011.09 2014.89,958.65 2174.89,958.65 2349.27,784.27 2479.04,784.27 2602.18,661.13 2879.19,661.13 3215,325.32 3215,246 3288.33,172.67 3288.33,162.29 3275.89,149.86 3256.33,149.86 v1(3237.53,168.66)
  Bottom w5.66: U18.20@1593.65,1033.2 1593.78,1033.07 v1@1621,1033.07 ; EC2.148@3190.08,-522.97 3190.08,-451.92 3210.83,-431.17 3210.83,141.95 v1(3237.53,168.66)
HSEC_VREFHI1_3V3: EC1.45 R154.1 | length 567.1
  Top Layer w5.66: EC1.45@664.83,-528.32 661.85,-525.35 661.85,-420.54 677.39,-405 732,-405 758.2,-378.8 758.2,-326.8 881.57,-203.43 893.65,-203.43 907,-190.08 R154.1@907,-103.02
ICSS1_INH: J6.26 R81.1 | length 103.5
  Bottom w5.66: J6.26@1306.63,2230.4 1365.24,2230.4 1378.24,2217.4 R81.1@1404.77,2217.4
ICSSM_MII0_COL: TP15.1 U16.25 | length 91.6
  Bottom w5.66: U16.25@2179.94,1125.59 2205.82,1125.59 2226.39,1146.17 TP15.1@2262.98,1146.17
ICSSM_MII0_CRS: TP20.1 U16.23 | length 95.9
  Bottom w5.66: U16.23@2179.94,1164.96 2205.41,1164.96 2236.45,1196 TP20.1@2262.98,1196
ICSSM_MII0_RX_DV: R11.1 R20.2 U1.38 U16.34 | length 1439.9
  SIG1 w6.66: v1(2371.14,1058.4) 2387.44,1074.69 2389.8,1077.05 2389.8,1084.59 2364.14,1110.25 2364.14,1117.79 2375.45,1129.1 2382.99,1129.1 2443.18,1068.91 2450.72,1068.91 2462.03,1080.22 2462.03,1087.77 2401.84,1147.95 2401.84,1155.49 2413.15,1166.8 2420.69,1166.8 2480.88,1106.62 2488.42,1106.62 2499.73,1117.93 2499.73,1125.47 2441.16,1184.04 2441.16,1191.58 2452.47,1202.89 2460.01,1202.89 2488.9,1174 2521,1174 2530,1183 2530,1212.61 2512.01,1230.6 2512.01,1249.2 2515.91,1253.1 2607.37,1253.1 v1(2623.14,1237.33)
  Bottom w5.66: U16.34@2179.94,948.43 2202.52,948.43 2223.2,927.75 2240.53,927.75 2243.36,927.75 2248.49,932.88 2248.49,950.32 2253.62,955.45 2269.02,955.45 2274.15,950.32 2274.15,932.88 2279.28,927.75 2301.99,927.75 2358.83,927.75 2364.6,933.52 2364.6,950.47 2347.77,967.3 2347.77,1018.32 2370.56,1041.12 2370.56,1057.81 v1(2371.14,1058.4) ; v1(2623.14,1237.33) R11.1@2623.14,1270.82 R20.2@2672.24,1270.82 2690.18,1270.82 2697,1264 2697,1213.31 2702.91,1207.41 U1.38@2702.91,1159.61
ICSSM_MII0_RXCLK: R4.1 U16.29 | length 907.5
  Bottom w5.66: U16.29@2179.94,1046.85 2198.69,1046.85 2228.07,1076.23 2373.23,1076.23 2380,1083 2380,1109 2373.95,1115.05 2338.02,1115.05 2330.3,1122.77 2330.3,1144.91 2337.46,1152.08 2376.6,1152.08 2382,1157.47 2382,1188 2376.67,1193.33 2355.79,1193.33 2350.46,1198.66 2350.46,1214.66 2355.79,1219.99 2376.67,1219.99 2382,1225.32 2382,1241.32 2376.67,1246.65 2355.79,1246.65 2350.46,1251.98 2350.46,1267.98 2355.79,1273.31 2376.67,1273.31 2382,1278.64 2382,1306.35 2385.65,1310 2401.85,1310 2405.5,1306.35 R4.1@2405.5,1050.91
ICSSM_MII0_RXD0: R6.1 R15.2 U1.33 U16.41 | length 1416.3
  Top Layer w5.66: v1(2151.97,770.25) 2180,798.27 2180,1206.08 2195.39,1221.47 2318.8,1221.47 v1(2331.93,1234.6)
  Bottom w5.66: U16.41@2105.14,853.94 2105.14,804.6 2139.03,770.71 2151.51,770.71 v1(2151.97,770.25) ; v1(2331.93,1234.6) 2331.93,1268.1 2353.27,1289.44 2353.27,1322.41 2360.86,1330 2460.36,1330 2467.6,1322.76 2467.6,1289.34 2460.06,1281.8 2426.51,1281.8 2418.16,1273.45 2418.16,1246.41 2428.29,1236.28 2464.62,1236.28 2475.93,1224.96 2475.93,1142.01 2482.94,1135 2497.05,1135 2501.95,1130.1 2504.35,1132.5 R6.1@2552.49,1132.5 2577.19,1132.5 2634.73,1074.97 U1.33@2657.63,1074.97
ICSSM_MII0_RXD1: R7.1 R16.2 U1.34 U16.39 | length 1418.2
  Top Layer w5.66: v1(2387.59,831.89) 2387.59,913.44 2436.66,962.51 v1(2436.66,1258.32)
  Bottom w5.66: U16.39@2144.51,853.94 2144.51,833.64 2179.14,799 2183.87,799 2210.92,799 2216.05,793.87 2216.05,752.11 2221.18,746.98 2236.58,746.98 2241.71,752.11 2241.71,795.49 2246.84,800.62 2262.24,800.62 2267.37,795.49 2267.37,741.21 2272.5,736.07 2287.9,736.07 2293.03,741.21 2293.03,795.49 2298.16,800.62 2313.56,800.62 2318.69,795.49 2318.69,741.21 2323.82,736.07 2339.22,736.07 2344.35,741.21 2344.35,793.87 2349.48,799 2352.31,799 2377.32,799 2387.59,809.27 v1(2387.59,831.89) ; v1@2434.07,1258.32 v1(2436.66,1258.32) 2499.44,1258.32 R16.2@2501.95,1260.82 2503.91,1258.85 2549.4,1258.85 R7.1@2551.36,1260.82 ; R7.1@2551.36,1256.89 2552.81,1255.44 2552.81,1236.77 2592.5,1197.08 2592.5,1135.1 2632.95,1094.65 U1.34@2657.63,1094.65
ICSSM_MII0_RXD2: R12.1 R21.2 U1.35 U16.38 | length 1415.5
  Top Layer w5.66: v1(2366.83,869.69) 2366.83,910.58 2424,967.75 2424,1245.07 2408.83,1260.24 2408.83,1344.1 2352.45,1400.48 2352.45,1447.97 2359.45,1454.97 2401.49,1454.97 2408.83,1447.63 v1(2408.83,1417)
  Bottom w5.66: U16.38@2179.94,869.69 2277.09,869.69 2358.93,869.69 v1(2366.83,869.69) ; v1(2408.83,1417) 2500.95,1417 R21.2@2501.95,1418 R12.1@2551.36,1418 2551.36,1414.06 2579.52,1385.9 2579.52,1231.17 2608.05,1202.65 2608.05,1140.94 2634.66,1114.34 U1.35@2657.63,1114.34
ICSSM_MII0_RXD3: R13.1 R22.2 U1.36 U16.36 | length 1416.8
  Top Layer w5.66: v1@2430.53,861.4 2471.36,902.23 2471.36,1297.93 2478.43,1305 2638.61,1305 2647,1313.39 2647,1373.11 2653.47,1379.57 v1(2672.24,1379.57)
  Bottom w5.66: U16.36@2179.94,909.06 2201.26,909.06 2208.28,902.03 2391.19,902.03 v1(2430.53,862.69) ; U1.36@2657.63,1134.02 2636.46,1134.02 2626.11,1144.38 2626.11,1203.95 2592.18,1237.87 2592.18,1383.11 2623.14,1414.06 R13.1@2623.14,1418 R22.2@2672.24,1418 v1(2672.24,1379.57)
ICSSM_MII0_RXER: R3.2 R9.1 R18.2 R119.1 U16.32 | length 1840.3
  SIG1 w6.66: v1(2318.29,987.8) 2356.5,1026 2430.26,1026 2517,1112.74 2517,1145 2527.85,1155.85 2528.8,1155.85 2558.79,1155.85 2564.12,1150.51 2564.12,1111.18 2569.45,1105.85 2585.45,1105.85 2590.78,1111.18 2590.78,1150.57 2596.11,1155.9 2612.11,1155.9 2617.44,1150.57 2617.44,1111.18 2622.77,1105.85 2638.77,1105.85 2644.1,1111.18 2644.1,1150.57 2649.43,1155.9 2665.43,1155.9 2670.76,1150.57 2670.76,1111.18 2676.09,1105.85 2692.09,1105.85 2697.42,1111.18 2697.42,1150.51 2702.75,1155.85 2736.29,1155.85 2898.69,1155.85 2914.84,1172 v1(2914.84,1270.78)
  Bottom w5.66: U16.32@2179.94,987.8 v1(2318.29,987.8) ; R119.1@2776.98,1582.81 2751.39,1582.81 2743.01,1574.43 2743.01,1532.89 2712.82,1502.71 2712.82,1396.32 2736.83,1372.31 2896.38,1372.31 2914.84,1353.85 v1(2914.84,1270.78) 2937.6,1270.78 R18.2@2937.65,1270.82 2938.26,1271.43 R9.1@2984.58,1271.43 2984.44,1271.28 R3.2@2984.44,1223.58
ICSSM_MII0_RXLINK: R8.1 R17.2 R116.1 U1.47 U16.27 | length 1727.4
  SIG1 w6.66: v1(2361.84,1170.83) 2380.99,1170.83 2477.74,1267.57 2618.82,1267.57 2649,1237.39 2649,1194.74 2673.35,1170.4 2802.72,1170.4 2820.74,1188.41 2820.74,1379.92 2847.29,1406.47 v1(2893.06,1406.47)
  Bottom w5.66: U16.27@2179.94,1086.22 2202.26,1086.22 2223.99,1107.95 2298.96,1107.95 2316.29,1125.28 2316.29,1158.26 2328.85,1170.83 v1(2361.84,1170.83) ; U1.47@2880.07,1159.61 2880.07,1180.46 2900.13,1200.51 3018.21,1200.51 3031.24,1213.54 R8.1@3031.24,1270.82 R17.2@3079.03,1270.82 3097.82,1270.82 3107,1280 3107,1348.38 3078.21,1377.16 2927.14,1377.16 2923.82,1380.48 2923.82,1405.21 R116.1@2924.42,1405.81 2923.77,1406.47 v1(2893.06,1406.47)
ICSSM_MII0_TXCLK: R1.1 U18.39 | length 1699.7
  SIG1 w6.66: v1(1222.4,1014.54) 1223.63,1014.54 1233.2,1024.11 1233.2,1122.66 1287.55,1177 1673.62,1177 1724.62,1126 1955.33,1126 2013.85,1184.53 2197.71,1184.53 2298,1084.24 2298,949.03 2303.95,943.07 2331.78,943.07 2342.98,954.28 2342.98,993.17 2361.72,1011.91 2412.74,1011.91 2424.94,999.7 2424.94,980.87 2419.31,975.24 v1(2405.5,975.24)
  Bottom w5.66: v1(1222.4,1014.54) 1222.91,1014.02 1246.68,1014.02 U18.39@1247.2,1013.51 ; v1(2405.5,975.24) R1.1@2405.5,1000.6
ICSSM_MII0_TXD0: U1.28 U18.38 | length 1934.5
  SIG1 w6.66: v1(1262.94,910) 1246.86,926.09 1246.86,1117 1293.2,1163.34 1667.96,1163.34 1718.96,1112.34 1971.61,1112.34 2002.25,1142.97 2176.94,1142.97 2256.72,1063.2 2256.72,969.7 2297.44,928.98 2337.62,928.98 2367.67,959.03 v1(2367.67,975.7)
  Bottom w5.66: v1(1262.94,910) U18.38@1262.94,978.08 ; v1(2367.67,975.7) 2387.13,956.24 2615.34,956.24 2635.64,976.54 U1.28@2657.63,976.54
ICSSM_MII0_TXD1: U1.27 U18.36 | length 1931
  SIG1 w6.66: v1(1301.84,910) 1260.52,951.33 1260.52,970.14 1283.83,993.45 1283.83,1008.98 1260.52,1032.3 1260.52,1111.34 1298.86,1149.68 1315.86,1149.68 1337.62,1127.92 1369.68,1127.92 1391.44,1149.68 1430.89,1149.68 1453.53,1127.04 1478.24,1127.04 1500.88,1149.68 1525.59,1149.68 1548.23,1127.04 1572.94,1127.04 1595.58,1149.68 1662.31,1149.68 1713.31,1098.68 2162.32,1098.68 2243.06,1017.94 2243.06,964.04 2305.06,902.04 2419.31,902.04 v1(2445.68,928.42)
  Bottom w5.66: v1@1301.84,910.46 1302.08,910.69 1302.08,977.84 U18.36@1302.32,978.08 ; v1(2445.68,928.42) 2460.85,943.58 2626.15,943.58 2639.43,956.85 U1.27@2657.63,956.85
ICSSM_MII0_TXD2: U1.26 U18.34 | length 1938.7
  SIG1 w6.66: v1(1341,910) 1341,954.96 1301.41,994.55 1301.41,1074.61 1339.82,1113.02 1655.87,1113.02 1707.36,1061.53 1730,1061.53 1733.33,1061.53 1738.66,1066.86 1738.66,1079.69 1743.99,1085.02 1759.99,1085.02 1765.32,1079.69 1765.32,1047.48 1770.65,1042.14 1786.65,1042.14 1791.98,1047.48 1791.98,1079.69 1797.31,1085.02 1813.31,1085.02 1818.64,1079.69 1818.64,1047.48 1823.97,1042.14 1839.97,1042.14 1845.3,1047.48 1845.3,1079.69 1850.63,1085.02 1866.63,1085.02 1871.96,1079.69 1871.96,1066.86 1877.29,1061.53 1898,1061.53 2046.97,1061.53 2058.27,1050.23 2176.68,1050.23 2206.57,1020.34 2206.57,981.22 2299.4,888.38 2432.01,888.38 v1(2445.68,902.05)
  Bottom w5.66: v1(1341,910) 1341.34,910.34 1341.34,977.74 U18.34@1341.69,978.08 ; v1(2445.68,902.05) 2474.17,930.53 2632.81,930.53 2639.45,937.17 U1.26@2657.63,937.17
ICSSM_MII0_TXD3: U1.25 U18.32 | length 1934
  SIG1 w6.66: v1(1578.39,853.75) 1726.75,853.75 1801.29,928.29 1948.66,928.29 2060.2,816.75 2216.94,816.75 2322.39,711.3 v1(2418,711.3)
  Bottom w5.66: U18.32@1381.06,978.08 1381.06,937.83 1362.7,919.47 1362.7,799.91 1371.63,790.98 1435.49,790.98 1464.98,790.98 1470.11,796.11 1470.11,848.92 1475.24,854.05 1490.64,854.05 1495.77,848.92 1495.77,796.11 1500.9,790.98 1515.62,790.98 1524.26,799.62 v1(1578.39,853.75) ; v1(2418,711.3) 2457.71,711.3 2461.02,714.62 2461.02,891.02 2487.49,917.48 U1.25@2657.63,917.48
ICSSM_MII0_TXEN: U1.37 U18.41 | length 1939
  SIG1 w6.66: v1(1211,1052.88) 1211,1119.78 1281.89,1190.66 1465,1190.66 1468.33,1190.66 1473.66,1195.99 1473.66,1218.5 1478.99,1223.83 1494.99,1223.83 1500.32,1218.5 1500.32,1195.99 1505.65,1190.66 1533,1190.66 1583.18,1190.66 1586.51,1190.66 1591.84,1195.99 1591.84,1229.33 1597.18,1234.66 1613.17,1234.66 1618.5,1229.33 1618.5,1195.99 1623.84,1190.66 1639.83,1190.66 1645.16,1195.99 1645.16,1229.33 1650.5,1234.66 1666.49,1234.66 1671.82,1229.33 1671.82,1195.99 1677.16,1190.66 1697.46,1190.66 1914.64,1190.66 1976.55,1252.57 2314.71,1252.57 2346.9,1284.76 2624.05,1284.76 v1(2671.48,1237.33)
  Bottom w5.66: v1(1211,1052.88) U18.41@1247.2,1052.88 ; v1(2671.48,1237.33) 2671.48,1236.09 2683.22,1224.34 U1.37@2683.22,1159.61
ICSSM_MII1_COL: J6.14 U17.25 | length 1776.4
  Top Layer w5.66: v1(1101.87,910.04) 1140.62,948.79 1140.62,1217.71 1134.15,1224.18 1091.13,1224.18 985.16,1330.15 985.16,2022.47 1098.51,2135.82 1315.42,2135.82 v1(1344.93,2165.33)
  Bottom w5.66: U17.25@1082.19,978.08 1082.19,929.72 v1(1101.87,910.04) ; J6.14@1306.63,2135.91 1337.15,2135.91 1344.93,2143.7 v1(1344.93,2165.33)
ICSSM_MII1_CRS: J6.30 U17.23 | length 3066
  SIG1 w6.66: v1(935,2304) 1516.98,2304 v1(1535.46,2285.52)
  Bottom w5.66: v1(935,2304) 935,2199.77 974.68,2160.09 974.68,1610.73 663.89,1299.94 663.89,975.32 897.53,741.68 1045.58,741.68 1121.56,817.66 U17.23@1121.56,978.08 ; J6.30@1306.63,2261.9 1514.13,2261.9 v1@1535.46,2283.23
ICSSM_MII1_RXCLK: J6.19 U17.29 | length 2182.8
  Top Layer w5.66: v1(1000,2191.03) 1000.51,2191.54 1106.41,2191.54 v1(1106.92,2192.06)
  Bottom w5.66: v1(1000,2191.03) 1000,1600.24 689.21,1289.45 689.21,986.95 907.59,768.57 1021.83,768.57 1028.8,775.55 1028.8,897.87 1003.45,923.22 U17.29@1003.45,978.08 ; v1(1106.92,2192.06) 1160.87,2192.06 1169.77,2183.16 J6.19@1199.93,2183.16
